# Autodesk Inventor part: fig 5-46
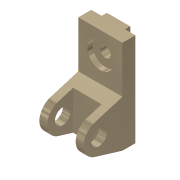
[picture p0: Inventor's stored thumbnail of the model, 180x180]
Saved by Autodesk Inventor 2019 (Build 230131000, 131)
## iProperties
Shininess: 65.0
Angle Display Precision: 2
Document Length Units: 11269
Document Angle Units: 11279
Document Time Units: 11290
Document Mass Units: 11283
Document Length Units Precision: 3
Document Angle Units Precision: 2
Created: 2001-11
Part Number: fig 5-46
Document SubType Name: Modeling
Designer: Renu Muthoo
Density: 1 g/cm^3
Material: Generic
Appearance: Metal-Titanium (Polished)
Density: 0.0
Volumn: 0.0
Area: 0.0
PropertySet Name: Model Information
Control State: 0
Master: False
Checked Out: False
Author: Renu Muthoo
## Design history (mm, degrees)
node "Sketch1"
sketch "Sketch2"
  geometry: L1 (33.257, 104.664)-(33.257, -75.336); L2 (33.257, -75.336)-(8.257, -75.336); L3 (8.257, -75.336)-(-45.451, -59.045); L4 (-45.451, -1.628)-(8.257, 14.664); L5 (8.257, 14.664)-(8.257, 104.664); L6 (8.257, 104.664)-(33.257, 104.664); C1 r 15 at (-36.743, -30.336); A1 r 30 centre (-36.743, -30.336) between (-45.451, -1.628) and (-45.451, -59.045)
  constraints: 12 end point, 2 centre point, 2 equal length, 2 parallel, 2 point on circle, 2 tangent, 1 coincident, 1 perpendicular, 1 vertical
  dimensions: "d0" = 180 distance of L1.start L1.end; "d1" = 30 radius of A1; "d2" = 25 distance of L5.end L1.start; "d3" = 45 distance from line of L2 A1.centre; "d4" = 70 distance from line of L1 A1.centre; "d5" = 30 diameter of C1
extrude "Extrusion1" new body sketch "Sketch2" distance "d6" = 85; taper "d7" = 0 deg
workplane "Work Plane1"
sketch "Sketch3"
  geometry: L1 (15, 62.364)-(70, 62.364); L2 (70, 62.364)-(70, -52.386); L3 (70, -52.386)-(15, -52.386); L4 (15, -52.386)-(15, 62.364); L5 (0, -45)-(0, -28.708) reference
  constraints: 8 end point, 2 parallel, 1 horizontal, 1 perpendicular
  dimensions: "d8" = 55 distance of L1.start L1.end; "d9" = 15 distance between parallel lines of L5 L4
extrude "Extrusion2" cut sketch "Sketch3" distance "d10" = 50; taper "d11" = 0 deg
sketch "Sketch4"
  geometry: L1 (0, 25)-(85, 25) reference; L2 (0, 0)-(0, 25) reference; L3 (20, 25)-(65, 25); L4 (65, 25)-(65, 35); L5 (65, 35)-(20, 35); L6 (20, 35)-(20, 25)
  constraints: 8 end point, 2 parallel, 1 horizontal, 1 perpendicular, 1 point on line
  dimensions: "d12" = 45 distance of L4.end L5.end; "d13" = 10 distance of L3.end L4.end; "d14" = 20 distance between parallel lines of L2 L6
extrude "Extrusion3" join sketch "Sketch4" stored distance "d15" = 50; taper "d16" = 0 deg
sketch "Sketch5"
  geometry: L1 (85, 0)-(85, 90) reference; L2 (0, 90)-(85, 90) reference; 1 further point
  dimensions: "d17" = 42 distance from line of L2 point (42.5, 48); "d18" = 42.5 distance from line of L1 point (42.5, 48)
hole "Hole1" sketch "Sketch5" at (42.5, 48) diameter "d19" = 20; stored, may be unused: countersink angle "d23" = 82 deg, drill point angle "d25" = 118 deg; dims "d20" = 6, "d21" = 50, "d22" = 10, "d24" = 8
workpoint "Work Point5"
body "Solid1"
